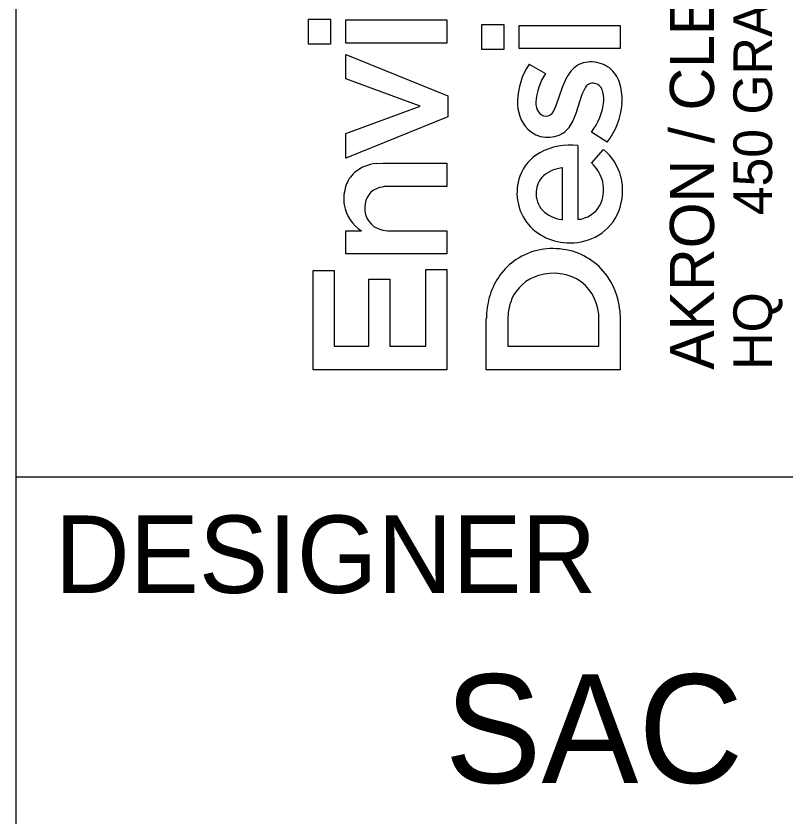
# Model space of a CAD drawing. Extents: x -1.9 to 34, y -1.1 to 22.
# Drawn here: x 32 to 32.993, y 2.061 to 3.094 of the extents above; entities that cross this region are included whole.
import ezdxf

# ---------------------------------------------------------------- set-up
doc = ezdxf.new("R2010")
doc.units = 0
doc.layers.add('SH_Border', color=7, linetype='Continuous')
doc.layers.add('SH_Data', color=7, linetype='Continuous')

msp = doc.modelspace()

# ---------------------------------------------------------------- linework, layer by layer
at = {"layer": 'SH_Border'}
for p, q in [((32, 0.5), (32, 21.5)), ((32, 2.5), (33.5, 2.5))]:
    msp.add_line(p, q, dxfattribs=at)
at = {"layer": 'SH_Data'}
for p, q in [((32.3771, 3.0582), (32.3771, 3.0903)), ((32.3771, 3.0903), (32.4054, 3.0903)), ((32.4054, 3.0903), (32.4054, 3.0582)), ((32.4254, 3.0594), (32.4254, 3.0893)), ((32.4254, 3.0893), (32.5557, 3.0893)), ((32.5557, 3.0893), (32.5557, 3.0594)), ((32.6005, 3.0511), (32.6005, 3.0832)), ((32.6005, 3.0832), (32.6289, 3.0832)), ((32.6289, 3.0832), (32.6289, 3.0511)), ((32.6489, 3.0523), (32.6489, 3.0822)), ((32.6489, 3.0822), (32.7792, 3.0822)), ((32.7792, 3.0822), (32.7792, 3.0523)), ((32.5557, 3.0594), (32.4254, 3.0594)), ((32.4054, 3.0582), (32.3771, 3.0582)), ((32.6289, 3.0511), (32.6005, 3.0511)), ((32.7792, 3.0523), (32.6489, 3.0523)), ((32.4254, 3.0133), (32.4254, 3.0446)), ((32.4254, 3.0446), (32.5567, 2.9913)), ((32.6615, 3.0321), (32.6827, 3.0203)), ((32.5212, 2.978), (32.4254, 3.0133)), ((32.7048, 3.0026), (32.7104, 3.0153)), ((32.6967, 2.9787), (32.7048, 3.0026)), ((32.7334, 3.001), (32.7298, 2.9933)), ((32.5567, 2.9913), (32.5567, 2.9644)), ((32.7298, 2.9933), (32.7221, 2.9688)), ((32.4254, 2.9429), (32.5212, 2.978)), ((32.693, 2.9712), (32.6967, 2.9787)), ((32.7221, 2.9688), (32.7182, 2.9592)), ((32.5567, 2.9644), (32.4254, 2.9109)), ((32.4254, 2.9109), (32.4254, 2.9429)), ((32.7621, 2.9314), (32.742, 2.9447)), ((32.7245, 2.9275), (32.7246, 2.8319)), ((32.7423, 2.9046), (32.7577, 2.922)), ((32.4644, 2.904), (32.4729, 2.9044)), ((32.4729, 2.9044), (32.5557, 2.9044)), ((32.5557, 2.9044), (32.5557, 2.8746)), ((32.7049, 2.8318), (32.7049, 2.8983)), ((32.5557, 2.8746), (32.4814, 2.8746)), ((32.7036, 2.8317), (32.7049, 2.8318)), ((32.4254, 2.7875), (32.4254, 2.8173)), ((32.4254, 2.8173), (32.4455, 2.8173)), ((32.4822, 2.8173), (32.5557, 2.8173)), ((32.5557, 2.8173), (32.5557, 2.7876)), ((32.5557, 2.7876), (32.4254, 2.7875)), ((32.383, 2.6379), (32.383, 2.766)), ((32.383, 2.766), (32.4101, 2.766)), ((32.4101, 2.766), (32.4101, 2.6683)), ((32.5286, 2.6683), (32.5286, 2.7672)), ((32.5286, 2.7672), (32.5557, 2.7672)), ((32.5557, 2.7672), (32.5557, 2.6379)), ((32.455, 2.6683), (32.455, 2.7549)), ((32.455, 2.7549), (32.4822, 2.7549)), ((32.4822, 2.7549), (32.4822, 2.6683)), ((32.6347, 2.7118), (32.6341, 2.7023)), ((32.7785, 2.715), (32.7792, 2.7021)), ((32.6064, 2.638), (32.6064, 2.704)), ((32.6341, 2.7023), (32.6341, 2.6684)), ((32.7515, 2.6683), (32.7515, 2.7024)), ((32.7792, 2.7021), (32.7792, 2.638)), ((32.4101, 2.6683), (32.455, 2.6683)), ((32.4822, 2.6683), (32.5286, 2.6683)), ((32.6341, 2.6684), (32.7515, 2.6683)), ((32.5557, 2.6379), (32.383, 2.6379)), ((32.7792, 2.638), (32.6064, 2.638))]:
    msp.add_line(p, q, dxfattribs=at)
for points in [[(32.3771, 3.0582), (32.3771, 3.0903), (32.4054, 3.0903), (32.4054, 3.0582)], [(32.4254, 3.0594), (32.4254, 3.0893), (32.5557, 3.0893), (32.5557, 3.0594)], [(32.6005, 3.0511), (32.6005, 3.0832), (32.6289, 3.0832), (32.6289, 3.0511)], [(32.6489, 3.0523), (32.6489, 3.0822), (32.7792, 3.0822), (32.7792, 3.0523)], [(32.4254, 2.9109), (32.4254, 2.9429), (32.5212, 2.978), (32.4254, 3.0133), (32.4254, 3.0446), (32.5567, 2.9913), (32.5567, 2.9644)], [(32.383, 2.6379), (32.383, 2.766), (32.4101, 2.766), (32.4101, 2.6683), (32.455, 2.6683), (32.455, 2.7549), (32.4822, 2.7549), (32.4822, 2.6683), (32.5286, 2.6683), (32.5286, 2.7672), (32.5557, 2.7672), (32.5557, 2.6379)]]:
    msp.add_lwpolyline(points, close=True, dxfattribs=at)
for points in [[(32.6615, 3.0321), (32.6827, 3.0203)], [(32.693, 2.9712), (32.6967, 2.9787), (32.7048, 3.0026), (32.7104, 3.0153)], [(32.7334, 3.001), (32.7298, 2.9933), (32.7221, 2.9688), (32.7182, 2.9592)], [(32.7621, 2.9314), (32.742, 2.9447)], [(32.7245, 2.9275), (32.7246, 2.8319)], [(32.7423, 2.9046), (32.7577, 2.922)], [(32.4644, 2.904), (32.4729, 2.9044), (32.5557, 2.9044), (32.5557, 2.8746), (32.4814, 2.8746)], [(32.7036, 2.8317), (32.7049, 2.8318), (32.7049, 2.8983)], [(32.4254, 2.7875), (32.4254, 2.8173), (32.4455, 2.8173)], [(32.4822, 2.8173), (32.5557, 2.8173), (32.5557, 2.7876), (32.4254, 2.7875)], [(32.7785, 2.715), (32.7792, 2.7021), (32.7792, 2.638), (32.6064, 2.638)], [(32.6347, 2.7118), (32.6341, 2.7023), (32.6341, 2.6684), (32.7515, 2.6683), (32.7515, 2.7024)], [(32.6064, 2.638), (32.6064, 2.704)]]:
    msp.add_lwpolyline(points, dxfattribs=at)
for centre, radius, start, end in [((32.7364, 2.9826), 0.0897, 146.531, 178.7571), ((32.7364, 2.9826), 0.0897, 146.531, 178.7571), ((32.7466, 2.9971), 0.0405, 125.5118, 153.4159), ((32.7466, 2.9971), 0.0405, 125.5118, 153.4159), ((32.7406, 3.0026), 0.0326, 80.1719, 122.5197), ((32.7406, 3.0026), 0.0326, 80.1719, 122.5197), ((32.7428, 2.9982), 0.0367, 47.7934, 84.6892), ((32.7428, 2.9982), 0.0367, 47.7934, 84.6892), ((32.7452, 2.9789), 0.0749, 146.5112, 176.9101), ((32.7452, 2.9789), 0.0749, 146.5112, 176.9101), ((32.7379, 2.9946), 0.0427, 14.9966, 46.2063), ((32.7379, 2.9946), 0.0427, 14.9966, 46.2063), ((32.7438, 2.9963), 0.0114, 76.6609, 155.7053), ((32.7438, 2.9963), 0.0114, 76.6609, 155.7053), ((32.744, 2.9951), 0.0126, 21.5098, 78.5262), ((32.744, 2.9951), 0.0126, 21.5098, 78.5262), ((32.7259, 2.9877), 0.0321, 354.5726, 22.068), ((32.7259, 2.9877), 0.0321, 354.5726, 22.068), ((32.7104, 2.9867), 0.0712, 355.8306, 15.3914), ((32.7104, 2.9867), 0.0712, 355.8306, 15.3914), ((32.6967, 2.9824), 0.0501, 177.5366, 222.7932), ((32.6967, 2.9824), 0.0501, 177.5366, 222.7932), ((32.6931, 2.9823), 0.0228, 178.4747, 211.0868), ((32.6931, 2.9823), 0.0228, 178.4747, 211.0868), ((32.6825, 2.9915), 0.0757, 321.811, 354.7969), ((32.6825, 2.9915), 0.0757, 321.811, 354.7969), ((32.6895, 2.9882), 0.0922, 321.9777, 355.8738), ((32.6895, 2.9882), 0.0922, 321.9777, 355.8738), ((32.6833, 2.9767), 0.0115, 212.2368, 268.3777), ((32.6833, 2.9767), 0.0115, 212.2368, 268.3777), ((32.6834, 2.9759), 0.0107, 267.716, 333.7337), ((32.6834, 2.9759), 0.0107, 267.716, 333.7337), ((32.681, 2.9758), 0.0408, 308.0877, 335.9874), ((32.681, 2.9758), 0.0408, 308.0877, 335.9874), ((32.686, 2.9753), 0.0375, 225.9854, 302.4797), ((32.686, 2.9753), 0.0375, 225.9854, 302.4797), ((32.7152, 2.8441), 0.0838, 83.615, 118.2876), ((32.7152, 2.8441), 0.0838, 83.615, 118.2876), ((32.7024, 2.8691), 0.0558, 118.8308, 160.6244), ((32.7024, 2.8691), 0.0558, 118.8308, 160.6244), ((32.7174, 2.8717), 0.0644, 13.5336, 51.3615), ((32.7174, 2.8717), 0.0644, 13.5336, 51.3615), ((32.4687, 2.8543), 0.0499, 94.9696, 130.2225), ((32.4687, 2.8543), 0.0499, 94.9696, 130.2225), ((32.7038, 2.8656), 0.0549, 19.0357, 45.4406), ((32.7038, 2.8656), 0.0549, 19.0357, 45.4406), ((32.7079, 2.8561), 0.0424, 94.008, 130.8817), ((32.7079, 2.8561), 0.0424, 94.008, 130.8817), ((32.4635, 2.8626), 0.0402, 132.2219, 161.6818), ((32.4635, 2.8626), 0.0402, 132.2219, 161.6818), ((32.7104, 2.8661), 0.0644, 160.5201, 215.7831), ((32.7104, 2.8661), 0.0644, 160.5201, 215.7831), ((32.7005, 2.8663), 0.0298, 132.9851, 177.179), ((32.7005, 2.8663), 0.0298, 132.9851, 177.179), ((32.7107, 2.8697), 0.047, 344.6059, 17.007), ((32.7107, 2.8697), 0.047, 344.6059, 17.007), ((32.7064, 2.8692), 0.0758, 339.3542, 13.3785), ((32.7064, 2.8692), 0.0758, 339.3542, 13.3785), ((32.4787, 2.8582), 0.056, 162.2736, 187.7919), ((32.4787, 2.8582), 0.056, 162.2736, 187.7919), ((32.4748, 2.8487), 0.025, 103.6865, 182.2187), ((32.4748, 2.8487), 0.025, 103.6865, 182.2187), ((32.4811, 2.8286), 0.046, 89.6049, 105.3284), ((32.4811, 2.8286), 0.046, 89.6049, 105.3284), ((32.7017, 2.865), 0.0311, 175.0013, 223.283), ((32.7017, 2.865), 0.0311, 175.0013, 223.283), ((32.7224, 2.8671), 0.035, 288.0077, 343.5508), ((32.7224, 2.8671), 0.035, 288.0077, 343.5508), ((32.4703, 2.858), 0.0476, 188.962, 238.7037), ((32.4703, 2.858), 0.0476, 188.962, 238.7037), ((32.4773, 2.8456), 0.0276, 175.5854, 255.1439), ((32.4773, 2.8456), 0.0276, 175.5854, 255.1439), ((32.7089, 2.8736), 0.0423, 225.0619, 262.7974), ((32.7089, 2.8736), 0.0423, 225.0619, 262.7974), ((32.7189, 2.8652), 0.0626, 300.9427, 338.7323), ((32.7189, 2.8652), 0.0626, 300.9427, 338.7323), ((32.7247, 2.8522), 0.0202, 269.7003, 294.8711), ((32.7247, 2.8522), 0.0202, 269.7003, 294.8711), ((32.7125, 2.8705), 0.0687, 217.7452, 271.6543), ((32.7125, 2.8705), 0.0687, 217.7452, 271.6543), ((32.4818, 2.8595), 0.0422, 254.0916, 270.5284), ((32.4818, 2.8595), 0.0422, 254.0916, 270.5284), ((32.7155, 2.8724), 0.0706, 269.2048, 300.3341), ((32.7155, 2.8724), 0.0706, 269.2048, 300.3341), ((32.6923, 2.7079), 0.0864, 81.194, 125.9984), ((32.6923, 2.7079), 0.0864, 81.194, 125.9984), ((32.6946, 2.7113), 0.0827, 37.8521, 82.402), ((32.6946, 2.7113), 0.0827, 37.8521, 82.402), ((32.6939, 2.7089), 0.0865, 127.2362, 165.148), ((32.6939, 2.7089), 0.0865, 127.2362, 165.148), ((32.6889, 2.7078), 0.054, 106.1881, 157.3861), ((32.6889, 2.7078), 0.054, 106.1881, 157.3861), ((32.6928, 2.6986), 0.0639, 55.6727, 107.2093), ((32.6928, 2.6986), 0.0639, 55.6727, 107.2093), ((32.6859, 2.7057), 0.0931, 5.7333, 37.304), ((32.6859, 2.7057), 0.0931, 5.7333, 37.304), ((32.6929, 2.705), 0.0587, 357.4662, 52.2665), ((32.6929, 2.705), 0.0587, 357.4662, 52.2665), ((32.7143, 2.7028), 0.1078, 164.7861, 179.3704), ((32.7143, 2.7028), 0.1078, 164.7861, 179.3704), ((32.6983, 2.7039), 0.0641, 157.3571, 172.9275), ((32.6983, 2.7039), 0.0641, 157.3571, 172.9275)]:
    msp.add_arc(centre, radius, start, end, dxfattribs=at)

# ---------------------------------------------------------------- texts
for s, height, p in [('450 GRANT ST., AKRON, OH  44311', 0.049846, (32.9749, 2.8374)), ('AKRON / CLEVELAND / COLUMBUS', 0.056969, (32.9001, 2.638)), ('HQ ', 0.04985, (32.9749, 2.638))]:
    msp.add_text(s, height=height, rotation=90, dxfattribs=at).set_placement(p)
for s, height, p in [('DESIGNER', 0.1, (32.05, 2.35)), ('SAC', 0.14, (32.5528, 2.105))]:
    msp.add_text(s, height=height, dxfattribs=at).set_placement(p)

doc.saveas('drawing.dxf')
